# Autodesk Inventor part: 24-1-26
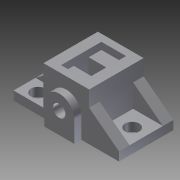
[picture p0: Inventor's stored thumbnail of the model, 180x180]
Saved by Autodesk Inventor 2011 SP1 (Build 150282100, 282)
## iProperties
Created: 2014-01
Part Number: 24-1-26
Document SubType Name: Modeling
Designer: Administrator
Density: 1 g/cm^3
Author: Administrator
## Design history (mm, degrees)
sketch "草图1"
  geometry: L1 (-30, 15.5)-(30, 15.5); L2 (30, 15.5)-(30, -15.5); L3 (30, -15.5)-(-30, -15.5); L4 (-30, -15.5)-(-30, 15.5); 3 further points
  constraints: 8 end point, 2 midpoint, 2 parallel, 1 horizontal, 1 horizontal alignment, 1 perpendicular, 1 vertical alignment
  dimensions: "d0" = 60 distance of L1.start L1.end; "d1" = 31 distance of L1.end L2.end
extrude "拉伸1" new body sketch "草图1" distance "d2" = 5; taper "d3" = 0 deg
sketch "草图2"
  geometry: L1 (-30, 15.5)-(30, 15.5) reference; L2 (30, -15.5)-(-30, -15.5) reference; L3 (-13, 15.5)-(13, 15.5); L4 (13, 15.5)-(13, -15.5); L5 (13, -15.5)-(-13, -15.5); L6 (-13, -15.5)-(-13, 15.5); 3 further points
  constraints: 8 end point, 4 midpoint, 2 parallel, 2 point on line, 1 horizontal, 1 perpendicular
  dimensions: "d4" = 26 distance between parallel lines of L4 L6
extrude "拉伸2" join sketch "草图2" distance "d5" = 22; taper "d6" = 0 deg
node "工作平面1"
sketch "草图3"
  geometry: L1 (60, 0)-(0, 0) reference; L2 (38.5, 12)-(38.5, 0); L3 (21.5, 12)-(21.5, 0); A1 r 8.5 centre (30, 12) between (38.5, 12) and (21.5, 12); 1 further point
  constraints: 4 end point, 2 perpendicular, 2 point on circle, 2 point on line, 2 tangent, 1 centre point
  dimensions: "d8" = 17 diameter of A1; "d9" = 12 distance of point (30, 0) A1.centre
extrude "拉伸3" join sketch "草图3" stored distance "d10" = 22; taper "d11" = 0 deg
hole "Hole1" diameter "d14" = 7; stored, may be unused: countersink angle "d18" = 90 deg, drill point angle "d20" = 120 deg; dims "d12" = 10, "d13" = 10, "d15" = 6, "d16" = 4, "d17" = 2, "d19" = 27
sketch "草图4"
  geometry: L1 (-7, 11.5)-(7, 11.5); L2 (7, 11.5)-(7, -11.5); L3 (7, -11.5)-(-7, -11.5); L4 (-7, -11.5)-(-7, 11.5); 3 further points
  constraints: 8 end point, 2 midpoint, 2 parallel, 1 horizontal, 1 horizontal alignment, 1 perpendicular, 1 vertical alignment
  dimensions: "d21" = 14 distance of L1.start L1.end; "d22" = 23 distance of L1.end L2.end
extrude "拉伸4" cut sketch "草图4" distance "d23" = 4; taper "d24" = 0 deg
sketch "草图5"
  geometry: L1 (-7, 11.5)-(-7, -11.5) reference; L2 (7, -11.5)-(7, 11.5) reference; L3 (-7, 4.25)-(7, 4.25); L4 (7, 4.25)-(7, -4.25); L5 (7, -4.25)-(-7, -4.25); L6 (-7, -4.25)-(-7, 4.25); 2 further points
  constraints: 8 end point, 2 parallel, 2 point on line, 1 horizontal, 1 horizontal alignment, 1 midpoint, 1 perpendicular
  dimensions: "d25" = 8.5 distance between parallel lines of L5 L3
extrude "拉伸5" cut sketch "草图5" distance "d26" = 30; taper "d27" = 0 deg
sketch "草图6"
  geometry: L1 (-17, 5)-(-17, 27) reference; L2 (0, 5)-(-17, 18); 1 further point
  constraints: 2 end point, 1 point on line
  dimensions: "d28" = 9 distance of L1.end L2.end
feature "加强筋1" sketch "草图6" dims "d29" = 1, "d30" = 6, "d31" = 0
mirror "镜像1"
sketch "草图7"
  geometry: L1 (30, 5)-(13, 5) reference; L2 (13, 5)-(13, 27) reference; L3 (30, 5)-(13, 18); L4 (30, 0)-(30, 5) reference; 1 further point
  constraints: 2 end point, 1 point on line
  dimensions: "d32" = 9 distance of L2.end L3.end
feature "加强筋2" sketch "草图7" dims "d33" = 1, "d34" = 6, "d35" = 0
hole "Hole2" diameter "d38" = 8; stored, may be unused: countersink angle "d42" = 90 deg, drill point angle "d44" = 120 deg; dims "d36" = 8, "d37" = 9.5, "d39" = 6, "d40" = 4, "d41" = 2, "d43" = 27
hole "Hole3" diameter "d47" = 8; stored, may be unused: countersink angle "d51" = 90 deg, drill point angle "d53" = 120 deg; dims "d45" = 6, "d46" = 8, "d48" = 6, "d49" = 4, "d50" = 2, "d52" = 27
mirror "镜像2"
node "实体1"
other parameters: "d7" = 4
